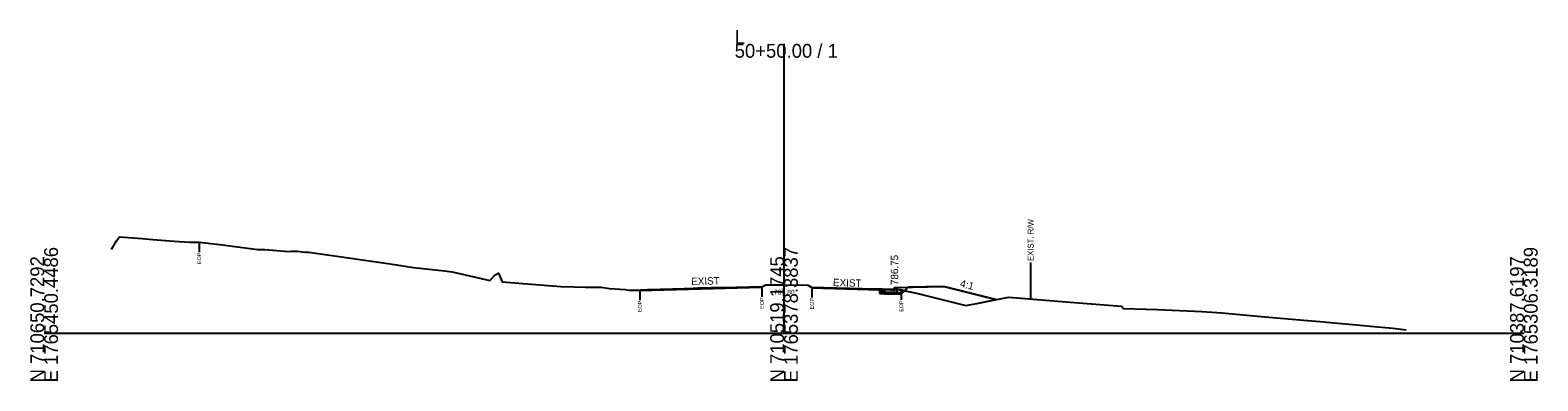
# Model space of a CAD drawing. Extents: x -26 to 5303, y -10 to 9578.
# Drawn here: x 3997.2 to 4302.8, y 490.3 to 561.5 of the extents above; entities that cross this region are included whole.
import ezdxf

# ---------------------------------------------------------------- set-up
doc = ezdxf.new("R2010")
doc.units = 0
for name, color, linetype in [('Exist Cross Section Cell', 7, 'Continuous'), ('Exist XS Ground Line', 7, 'Continuous'), ('Old_Level_10', 7, 'Continuous'), ('Old_Level_3', 7, 'Continuous'), ('Prop CMT Conc Surface', 7, 'Continuous'), ('Prop CMT Concrete Structures', 7, 'Continuous'), ('Prop CMT Pvmt Course 1', 7, 'Continuous'), ('Prop CMT Pvmt Course 1 CG', 7, 'Continuous'), ('Prop CMT Pvmt Course 2', 7, 'Continuous'), ('Prop CMT Pvmt Course 3', 7, 'Continuous'), ('Prop CMT Pvmt Surface', 7, 'Continuous'), ('Prop CMT Slope Grass', 7, 'Continuous'), ('Prop CMT Subgrade Earthwork', 7, 'Continuous'), ('Prop XS Earthwork Shape', 7, 'Continuous'), ('Prop XS Hydro Elevations', 7, 'Continuous'), ('Prop XS SE Text', 7, 'Continuous'), ('Prop XS Side Slope Text', 7, 'Continuous')]:
    doc.layers.add(name, color=color, linetype=linetype)

msp = doc.modelspace()

# ---------------------------------------------------------------- linework, layer by layer
at = {"layer": 'Exist Cross Section Cell'}
for p, q in [((4150, 500), (4150, 558.7)), ((4000, 500), (4150, 500)), ((4150, 500), (4300, 500))]:
    msp.add_line(p, q, dxfattribs=at)
at = {"layer": 'Exist XS Ground Line'}
msp.add_lwpolyline([(4013.64, 516.98), (4014.66, 518.71), (4015.26, 519.57), (4019.89, 519.18), (4022.01, 519.01), (4026.39, 518.69), (4029.47, 518.46), (4029.82, 518.43), (4031.43, 518.47), (4035.64, 517.97), (4042.81, 517.05), (4043.17, 516.96), (4043.58, 516.96), (4044.77, 516.96), (4049.55, 516.57), (4050.13, 516.63), (4051.3, 516.66), (4052.9, 516.46), (4053.66, 516.42), (4055.56, 516.19), (4070.15, 514.08), (4074.88, 513.3), (4081.18, 512.63), (4082.71, 512.41), (4090.36, 510.69), (4091.43, 511.84), (4092.13, 512.19), (4092.85, 510.4), (4103.05, 509.57), (4104.75, 509.46), (4107.4, 509.37), (4109.74, 509.33), (4112.9, 509.33), (4114.59, 509.07), (4117.78, 508.85), (4118.56, 508.74), (4118.87, 508.73), (4120.78, 508.72), (4122.21, 508.75), (4123.22, 508.79), (4124.83, 508.84), (4126.78, 508.93), (4127.68, 508.96), (4128.42, 508.99), (4130.53, 509.07), (4131.63, 509.12), (4132.56, 509.16), (4133.27, 509.17), (4134.24, 509.21), (4134.55, 509.22), (4135.31, 509.24), (4136.23, 509.25), (4139.08, 509.27), (4139.39, 509.27), (4141.93, 509.32), (4144.03, 509.36), (4144.77, 509.37), (4145.52, 509.39), (4146.3, 509.82), (4147.21, 509.82), (4150, 509.8), (4154.85, 509.76), (4155.65, 509.29), (4156.69, 509.25), (4157.41, 509.22), (4159.25, 509.17), (4159.64, 509.16), (4161.89, 509.09), (4164.85, 509.02), (4166.62, 508.96), (4167.59, 508.95), (4168.46, 508.94), (4169.24, 508.92), (4170.4, 508.87), (4171.47, 508.87), (4172.14, 508.85), (4172.59, 508.83), (4173.34, 508.8), (4173.76, 508.79), (4174.28, 508.64), (4176.86, 508.12), (4184.72, 506.13), (4186.89, 505.59), (4189.1, 506.02), (4195.49, 507.3), (4209.73, 506.13), (4218.4, 505.49), (4218.82, 504.99), (4225.74, 504.78), (4234.7, 504.41), (4238.77, 504.09), (4246.71, 503.39), (4256.17, 502.57), (4258.67, 502.34), (4260.79, 502.15), (4266.04, 501.68), (4268.91, 501.43), (4273.41, 501), (4276.12, 500.69)], dxfattribs=at)
at = {"layer": 'Old_Level_10'}
for p, q in [((4031.43, 518.47), (4031.43, 516.42)), ((4200, 514.33), (4200, 506.93)), ((4120.78, 508.72), (4120.78, 506.67)), ((4145.52, 509.39), (4145.52, 507.34)), ((4155.65, 509.29), (4155.65, 507.24)), ((4173.76, 508.79), (4173.76, 506.74))]:
    msp.add_line(p, q, dxfattribs=at)
at = {"layer": 'Prop CMT Conc Surface'}
for points in [[(4170.4, 508.89), (4172.4, 508.75)], [(4172.4, 508.75), (4172.4, 509.25), (4172.9, 509.25)]]:
    msp.add_lwpolyline(points, dxfattribs=at)
at = {"layer": 'Prop CMT Concrete Structures'}
for points in [[(4170.4, 508.89), (4172.4, 508.75), (4172.4, 509.25), (4172.9, 509.25)], [(4172.9, 509.25), (4172.9, 508.23), (4170.4, 508.31)], [(4170.4, 508.31), (4170.4, 508.89)]]:
    msp.add_lwpolyline(points, dxfattribs=at)
at = {"layer": 'Prop CMT Pvmt Course 1'}
for p, q in [((4145.52, 509.26), (4120.78, 508.59)), ((4155.65, 509.16), (4169.4, 508.79))]:
    msp.add_line(p, q, dxfattribs=at)
at = {"layer": 'Prop CMT Pvmt Course 1 CG'}
for points in [[(4170.4, 508.31), (4173.4, 508.22), (4173.74, 507.88)], [(4170.4, 507.98), (4170.4, 508.31)], [(4173.74, 507.88), (4170.4, 507.98)]]:
    msp.add_lwpolyline(points, dxfattribs=at)
at = {"layer": 'Prop CMT Pvmt Course 2'}
for points in [[(4169.4, 508.34), (4169.4, 508.67)], [(4169.4, 508.67), (4170.4, 508.64)], [(4170.4, 508.31), (4169.4, 508.34)], [(4170.4, 508.64), (4170.4, 508.31)]]:
    msp.add_lwpolyline(points, dxfattribs=at)
at = {"layer": 'Prop CMT Pvmt Course 3'}
for points in [[(4169.4, 508.34), (4170.4, 508.31)], [(4169.4, 508.01), (4169.4, 508.34)], [(4170.4, 507.98), (4169.4, 508.01)], [(4170.4, 508.31), (4170.4, 507.98)]]:
    msp.add_lwpolyline(points, dxfattribs=at)
at = {"layer": 'Prop CMT Pvmt Surface'}
for p, q in [((4145.52, 509.39), (4120.78, 508.72)), ((4155.65, 509.29), (4170.4, 508.89))]:
    msp.add_line(p, q, dxfattribs=at)
at = {"layer": 'Prop CMT Slope Grass'}
msp.add_lwpolyline([(4172.9, 509.25), (4182.4, 509.44), (4192.98, 506.8)], dxfattribs=at)
at = {"layer": 'Prop CMT Subgrade Earthwork'}
msp.add_line((4169.4, 508.01), (4169.4, 508.92), dxfattribs=at)
for points in [[(4169.4, 508.01), (4170.4, 507.98)], [(4170.4, 507.98), (4173.74, 507.88), (4175.17, 509.3)]]:
    msp.add_lwpolyline(points, dxfattribs=at)
at = {"layer": 'Prop XS Earthwork Shape'}
for points in [[(4120.78, 508.72), (4122.21, 508.75), (4122.33, 508.76)], [(4126.1, 508.89), (4127.94, 508.97), (4128.42, 508.99), (4129.78, 509.04), (4130.53, 509.07), (4131.63, 509.12), (4132.56, 509.16), (4133.27, 509.17), (4134.24, 509.21), (4134.55, 509.22), (4135.31, 509.24), (4136.23, 509.25), (4139.08, 509.27), (4140.83, 509.3), (4141.93, 509.32), (4142.68, 509.33), (4144.03, 509.36), (4144.77, 509.37), (4145.52, 509.39), (4122.33, 508.76), (4123.22, 508.79), (4124.26, 508.83), (4124.83, 508.84)], [(4123.22, 508.79), (4124.26, 508.83), (4124.83, 508.84), (4126.1, 508.89), (4127.94, 508.97), (4128.42, 508.99), (4129.78, 509.04), (4130.53, 509.07), (4131.63, 509.12), (4132.56, 509.16), (4133.27, 509.17), (4134.24, 509.21), (4134.55, 509.22), (4135.31, 509.24), (4136.23, 509.25), (4139.08, 509.27), (4140.83, 509.3), (4141.93, 509.32), (4142.68, 509.33), (4144.03, 509.36), (4144.77, 509.37), (4145.52, 509.39), (4122.33, 508.76)], [(4161.89, 509.09), (4162.93, 509.06), (4164.85, 509.02), (4167.59, 508.95), (4168.43, 508.94), (4155.65, 509.29), (4156.69, 509.25), (4157.41, 509.22), (4159.25, 509.17), (4159.64, 509.16), (4161.09, 509.12)], [(4155.65, 509.29), (4156.69, 509.25), (4157.41, 509.22), (4159.25, 509.17), (4159.64, 509.16), (4161.09, 509.12), (4161.89, 509.09), (4162.93, 509.06), (4164.85, 509.02), (4167.59, 508.95), (4168.43, 508.94)], [(4168.43, 508.94), (4168.46, 508.94), (4169.24, 508.93), (4169.4, 508.92)], [(4168.46, 508.94), (4169.24, 508.93), (4169.4, 508.92), (4168.43, 508.94)], [(4170.4, 507.98), (4173.74, 507.88), (4174.47, 508.6), (4174.28, 508.64), (4173.76, 508.79), (4173.34, 508.8), (4172.59, 508.83), (4172.4, 508.84), (4172.4, 508.75), (4170.69, 508.87), (4170.4, 508.87), (4169.98, 508.9), (4169.4, 508.92), (4169.4, 508.01)], [(4169.98, 508.9), (4170.4, 508.87), (4170.69, 508.87), (4172.4, 508.75), (4172.4, 508.84), (4172.59, 508.83), (4173.34, 508.8), (4173.76, 508.79), (4174.28, 508.64), (4174.47, 508.6), (4173.74, 507.88), (4170.4, 507.98), (4169.4, 508.01), (4169.4, 508.92)], [(4172.4, 508.75), (4172.4, 508.84), (4172.14, 508.85), (4171.47, 508.87), (4170.69, 508.87)], [(4171.47, 508.87), (4172.14, 508.85), (4172.4, 508.84), (4172.4, 508.75), (4170.69, 508.87)], [(4174.47, 508.6), (4176.86, 508.12), (4184.72, 506.13), (4186.89, 505.59), (4189.1, 506.02), (4192.98, 506.8), (4182.4, 509.44), (4175.17, 509.3)], [(4176.86, 508.12), (4184.72, 506.13), (4186.89, 505.59), (4189.1, 506.02), (4192.98, 506.8), (4182.4, 509.44), (4175.17, 509.3), (4174.47, 508.6)]]:
    msp.add_lwpolyline(points, close=True, dxfattribs=at)

# ---------------------------------------------------------------- texts
at = {"layer": 'Exist Cross Section Cell'}
for s, p in [('L', (4140, 558.7)), ('50+50.00 / 1', (4140, 555.9))]:
    msp.add_text(s, height=2.8, dxfattribs=at).set_placement(p)
for s, p in [('E 1765450.4486', (4002.8, 490)), ('E 1765378.3837', (4152.8, 490)), ('E 1765306.3189', (4302.8, 490)), ('N 710650.7292', (4000, 490)), ('N 710519.1745', (4150, 490)), ('N 710387.6197', (4300, 490))]:
    msp.add_text(s, height=2.8, rotation=90, dxfattribs=at).set_placement(p)
at = {"layer": 'Old_Level_10'}
for s, height, p in [('EXIST. R/W', 1.181, (4200.59, 514.63)), ('EOP', 0.787, (4031.82, 514.02)), ('EOP', 0.787, (4121.17, 504.27)), ('EOP', 0.787, (4145.91, 504.94)), ('EOP', 0.787, (4156.05, 504.84)), ('EOP', 0.787, (4174.16, 504.34))]:
    msp.add_text(s, height=height, rotation=90, dxfattribs=at).set_placement(p)
at = {"layer": 'Old_Level_3'}
msp.add_text('787.80', height=1, dxfattribs=at).set_placement((4147.95, 507.8))
at = {"layer": 'Prop XS Hydro Elevations'}
msp.add_text('786.75', height=1.5, rotation=90, dxfattribs=at).set_placement((4173.15, 509.75))
at = {"layer": 'Prop XS SE Text'}
for rotation, p in [(1.5504, (4131.19, 509.74)), (358.2816, (4159.91, 509.55))]:
    msp.add_text('EXIST', height=1.5, rotation=rotation, dxfattribs=at).set_placement(p)
at = {"layer": 'Prop XS Side Slope Text'}
msp.add_text('4:1', height=1.5, rotation=345.9638, dxfattribs=at).set_placement((4185.59, 509.42))

doc.saveas('drawing.dxf')
